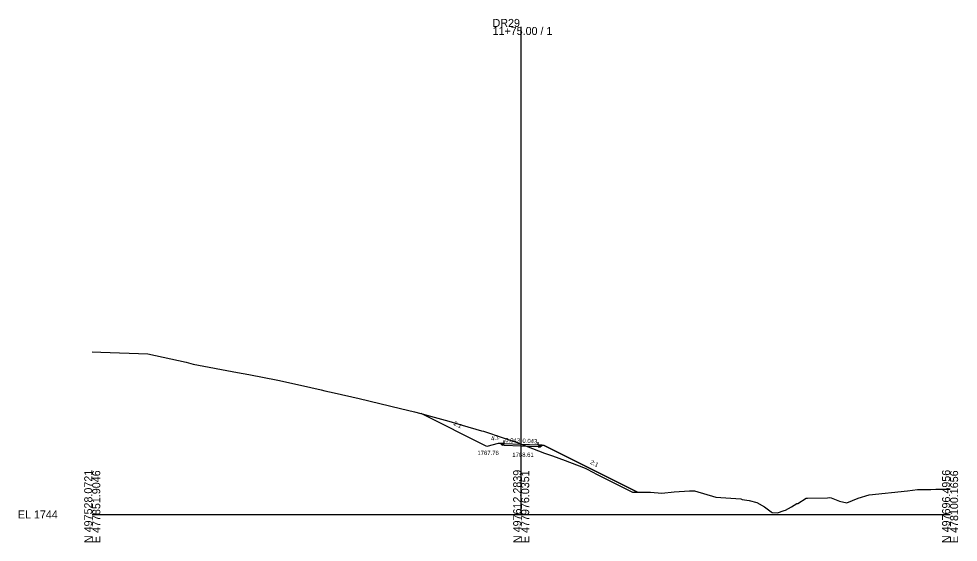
# Model space of a CAD drawing. Extents: x -26 to 303, y -10 to 4734.
# Drawn here: x -25.7 to 302.8, y 3490.3 to 3673.2 of the extents above; entities that cross this region are included whole.
import ezdxf

# ---------------------------------------------------------------- set-up
doc = ezdxf.new("R2010")
doc.units = 0
for name, color, linetype in [('Exist Cross Section Cell', 7, 'Continuous'), ('Exist XS Center Line Elevation Label', 7, 'Continuous'), ('Exist XS Ground Line', 7, 'Continuous'), ('Prop XS Ditch Slope Text', 7, 'Continuous'), ('Prop XS Ditch Standard Text', 7, 'Continuous'), ('Prop XS Dump Level', 7, 'Continuous'), ('Prop XS Earthwork Shape', 7, 'Continuous'), ('Prop XS EOT Tick Mark', 7, 'Continuous'), ('Prop XS Finish Grade', 7, 'Continuous'), ('Prop XS Finish Grade Earthwork', 7, 'Continuous'), ('Prop XS Finish Grade Pavement', 7, 'Continuous'), ('Prop XS Pvmt Edge Slope', 7, 'Continuous'), ('Prop XS SE Text', 7, 'Continuous'), ('Prop XS Shoulder Borrow Shape', 7, 'Continuous'), ('Prop XS Side Slope Text', 7, 'Continuous'), ('Prop XS Subgrade Earthwork', 7, 'Continuous')]:
    doc.layers.add(name, color=color, linetype=linetype)

msp = doc.modelspace()

# ---------------------------------------------------------------- linework, layer by layer
at = {"layer": 'Exist Cross Section Cell'}
for p, q in [((150, 3500), (150, 3670.33)), ((0, 3500), (150, 3500)), ((150, 3500), (300, 3500))]:
    msp.add_line(p, q, dxfattribs=at)
at = {"layer": 'Exist XS Ground Line'}
msp.add_lwpolyline([(0, 3556.78), (2.99, 3556.7), (19.4, 3556.17), (32.81, 3553.2), (35.29, 3552.45), (50.83, 3549.6), (54.77, 3548.92), (64.89, 3546.88), (72.81, 3545.18), (80.04, 3543.5), (81.39, 3543.16), (84.55, 3542.45), (93.34, 3540.54), (100.56, 3538.8), (107.75, 3537.06), (112.65, 3535.87), (114.95, 3535.25), (118.34, 3534.34), (122.15, 3533.29), (124.73, 3532.55), (129.35, 3531.21), (136.15, 3529.27), (136.82, 3529.07), (143.75, 3526.76), (148.91, 3525.02), (150, 3524.61), (150.95, 3524.26), (153.97, 3523.1), (158.15, 3521.47), (160.99, 3520.5), (165.35, 3518.89), (171.78, 3516.41), (172.56, 3516.11), (173.08, 3515.84), (176.57, 3513.98), (188.99, 3507.78), (195.19, 3507.81), (199.23, 3507.44), (203.55, 3507.93), (208.88, 3508.31), (210.23, 3508.25), (210.6, 3508.2), (218.1, 3506.06), (226.8, 3505.41), (227.3, 3505.18), (229.75, 3504.83), (232.47, 3504.23), (235.09, 3502.66), (237.38, 3500.89), (237.72, 3500.71), (239.66, 3500.6), (241.98, 3501.36), (242.39, 3501.5), (244.49, 3502.66), (246.45, 3503.78), (246.8, 3503.85), (249.69, 3505.69), (250.14, 3505.69), (257.13, 3505.86), (257.99, 3505.89), (258.38, 3505.75), (261.33, 3504.64), (263.86, 3504.01), (267.83, 3505.66), (271.74, 3506.82), (285.12, 3508.29), (288.62, 3508.68), (289.67, 3508.71), (290.44, 3508.73), (290.8, 3508.74), (291.34, 3508.75), (293.24, 3508.77), (295.03, 3508.82), (296.3, 3508.85), (297.63, 3508.88), (298.65, 3508.9), (299.36, 3508.91), (300, 3508.93)], dxfattribs=at)
at = {"layer": 'Prop XS Dump Level'}
for p, q in [((144, 3524.79), (150, 3524.54)), ((150, 3524.54), (156, 3524.28))]:
    msp.add_line(p, q, dxfattribs=at)
at = {"layer": 'Prop XS Earthwork Shape'}
for points in [[(143.75, 3526.76), (148.91, 3525.02), (150, 3524.61), (150.95, 3524.26), (152.21, 3523.78), (150, 3523.87), (144, 3524.12), (143.36, 3524.15), (142.74, 3524.77), (142, 3524.76), (138, 3523.76), (115.08, 3535.22), (118.34, 3534.34), (122.15, 3533.29), (124.73, 3532.55), (129.35, 3531.21), (136.15, 3529.27), (136.82, 3529.07)], [(122.15, 3533.29), (124.73, 3532.55), (129.35, 3531.21), (136.15, 3529.27), (136.82, 3529.07), (143.75, 3526.76), (148.91, 3525.02), (150, 3524.61), (150.95, 3524.26), (152.21, 3523.78), (150, 3523.87), (144, 3524.12), (143.36, 3524.15), (142.74, 3524.77), (142, 3524.76), (138, 3523.76), (115.08, 3535.22), (118.34, 3534.34)], [(152.21, 3523.78), (153.97, 3523.1), (158.15, 3521.47), (160.99, 3520.5), (165.35, 3518.89), (171.78, 3516.41), (172.56, 3516.11), (173.08, 3515.84), (176.57, 3513.98), (188.99, 3507.78), (190.66, 3507.79), (158, 3524.12), (157.29, 3524.18), (156.7, 3523.58), (156, 3523.61)], [(152.21, 3523.78), (153.97, 3523.1), (158.15, 3521.47), (160.99, 3520.5), (165.35, 3518.89), (171.78, 3516.41), (172.56, 3516.11), (173.08, 3515.84), (176.57, 3513.98), (188.99, 3507.78), (190.66, 3507.79), (158, 3524.12), (157.29, 3524.18), (156.7, 3523.58), (156, 3523.61)]]:
    msp.add_lwpolyline(points, close=True, dxfattribs=at)
at = {"layer": 'Prop XS EOT Tick Mark'}
for p, q in [((144, 3524.79), (144, 3525.79)), ((156, 3524.28), (156, 3525.28))]:
    msp.add_line(p, q, dxfattribs=at)
at = {"layer": 'Prop XS Finish Grade'}
for p, q in [((144, 3524.79), (142.74, 3524.77)), ((156, 3524.28), (157.29, 3524.18))]:
    msp.add_line(p, q, dxfattribs=at)
at = {"layer": 'Prop XS Finish Grade Earthwork'}
for p, q in [((138, 3523.76), (115.08, 3535.22)), ((142, 3524.76), (138, 3523.76)), ((142.74, 3524.77), (142, 3524.76)), ((157.29, 3524.18), (158, 3524.12)), ((158, 3524.12), (190.66, 3507.79))]:
    msp.add_line(p, q, dxfattribs=at)
at = {"layer": 'Prop XS Finish Grade Pavement'}
for p, q in [((144, 3524.79), (150, 3524.54)), ((150, 3524.54), (156, 3524.28))]:
    msp.add_line(p, q, dxfattribs=at)
at = {"layer": 'Prop XS Pvmt Edge Slope'}
for p, q in [((144, 3524.79), (143.36, 3524.15)), ((156, 3524.28), (156.7, 3523.58))]:
    msp.add_line(p, q, dxfattribs=at)
at = {"layer": 'Prop XS Shoulder Borrow Shape'}
for points in [[(144, 3524.79), (142.74, 3524.77), (143.36, 3524.15)], [(156.7, 3523.58), (157.29, 3524.18), (156, 3524.28)]]:
    msp.add_lwpolyline(points, close=True, dxfattribs=at)
at = {"layer": 'Prop XS Subgrade Earthwork'}
for p, q in [((143.36, 3524.15), (142.74, 3524.77)), ((144, 3524.12), (143.36, 3524.15)), ((150, 3523.87), (144, 3524.12)), ((156, 3523.61), (150, 3523.87)), ((156, 3523.61), (156.7, 3523.58)), ((156.7, 3523.58), (157.29, 3524.18))]:
    msp.add_line(p, q, dxfattribs=at)

# ---------------------------------------------------------------- texts
at = {"layer": 'Exist Cross Section Cell'}
for s, p in [('DR29', (140, 3670.33)), ('11+75.00 / 1', (140, 3667.53)), ('EL 1744', (-26, 3498.6))]:
    msp.add_text(s, height=2.8, dxfattribs=at).set_placement(p)
for s, p in [('N 497528.0721', (0, 3490)), ('N 497612.2839', (150, 3490)), ('N 497696.4956', (300, 3490)), ('E 477851.9046', (2.8, 3490)), ('E 477976.0351', (152.8, 3490)), ('E 478100.1656', (302.8, 3490))]:
    msp.add_text(s, height=2.8, rotation=90, dxfattribs=at).set_placement(p)
at = {"layer": 'Exist XS Center Line Elevation Label'}
msp.add_text('1768.61', height=1.5, dxfattribs=at).set_placement((146.91, 3520.11))
at = {"layer": 'Prop XS Ditch Slope Text'}
msp.add_text('4:1', height=1.5, rotation=14.0362, dxfattribs=at).set_placement((139.64, 3525.71))
at = {"layer": 'Prop XS Ditch Standard Text'}
msp.add_text('1767.76', height=1.5, dxfattribs=at).set_placement((134.69, 3520.76))
at = {"layer": 'Prop XS Dump Level'}
for p in [(142, 3524.72), (158, 3524.08)]:
    msp.add_text('Case1', height=0.04, dxfattribs=at).set_placement(p)
at = {"layer": 'Prop XS SE Text'}
for p in [(144.41, 3525.27), (150.41, 3525.02)]:
    msp.add_text('0.043', height=1.5, rotation=357.5614, dxfattribs=at).set_placement(p)
at = {"layer": 'Prop XS Side Slope Text'}
for p in [(126.2, 3531.33), (173.99, 3517.8)]:
    msp.add_text('2:1', height=1.5, rotation=333.4349, dxfattribs=at).set_placement(p)

doc.saveas('drawing.dxf')
